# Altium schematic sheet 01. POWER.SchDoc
size A4; DrawnBy: Jaden; DocumentNumber: 1; SheetNumber: 1; SheetTotal: 6
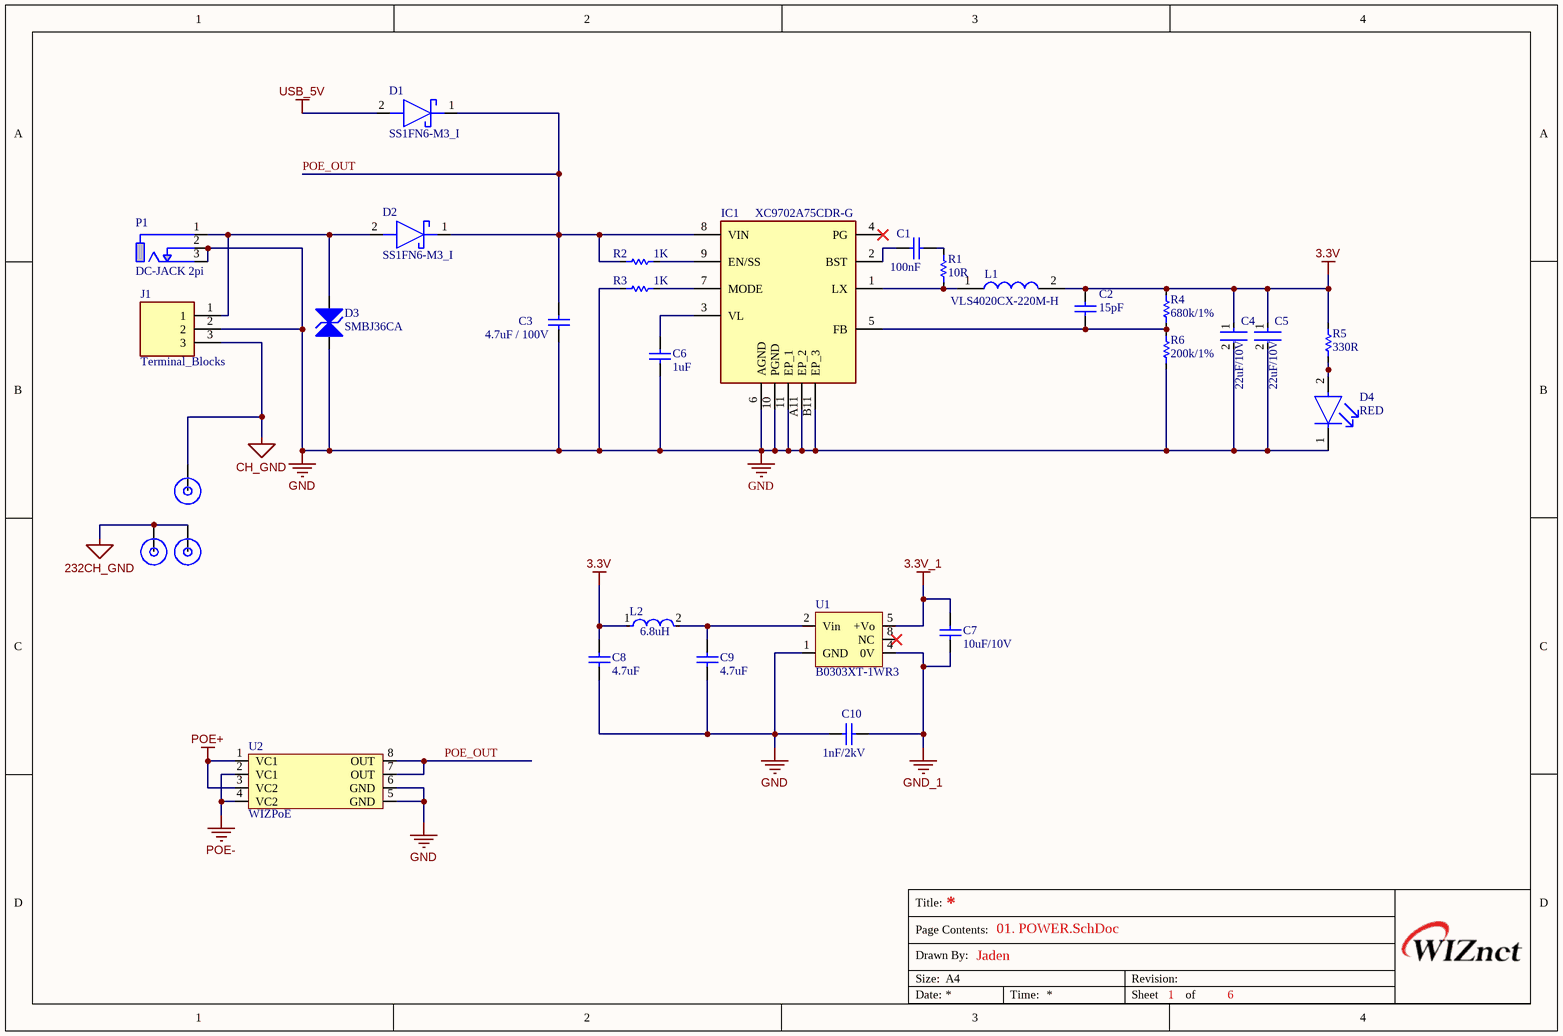
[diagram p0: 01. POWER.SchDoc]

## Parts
C1  100nF  [CAP-0402]
C2  15pF  [CAP-0402]
C3  4.7uF / 100V  [CAP-1210]
C4  22uF/10V  [CAP-1206]
C5  22uF/10V  [CAP-1206]
C6  1uF  [CAP-0603-1]
C7  10uF/10V  [CAP-0603-3]
C8  4.7uF  [CAP-0603-3]
C9  4.7uF  [CAP-0603-3]
C10  1nF/2kV  [CAP-1808]
D1  SS1FN6-M3_I  [SODFL3718X108N]
D2  SS1FN6-M3_I  [SODFL3718X108N]
D3  SMBJ36CA  [DO-214AA/SMB(TVS)]
D4  RED  [KLH-117]
H1  PCB Hole  [M3_HOLE]  (value not drawn)  (no BOM)
H2  PCB Hole  [M3_HOLE]  (value not drawn)  (no BOM)
H3  PCB Hole  [M3_HOLE]  (value not drawn)  (no BOM)
IC1  XC9702A75CDR-G  [XC9135B18CDRG]
J1  Terminal_Blocks  [1803280]
L1  VLS4020CX-220M-H  [XAL40XX]
L2  6.8uH  [FP-SRN2512-MFG]
P1  DC-JACK 2pi  [DC-JACK 2pi]
R1  10R  [RES-0402]
R2  1K  [RES-0402]
R3  1K  [RES-0402]
R4  680k/1%  [RES-0402]
R5  330R  [RES-0402]
R6  200k/1%  [RES-0402]
U1  B0303XT-1WR3  [IB05_XT-W75R3]
U2  WIZPoE  [WIZPoE]

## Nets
3.3V: C2.2 C4.1 C5.1 C8.2 L1.2 L2.1 R4.2 R5.2
3.3V_1: C7.2 U1.5(+Vo)
232CH_GND: H2.1 H3.1
CH_GND: H1.1 J1.3
GND: C3.1 C4.2 C5.2 C6.1 C8.1 C9.1 C10.2 D3.1(A1) D4.1(C) IC1.6(AGND) IC1.10(PGND) IC1.11(EP_1) IC1.A11(EP_2) IC1.B11(EP_3) J1.2 P1.2(GND) P1.3(GND) R3.1 R6.1 U1.1(GND) U2.5(GND) U2.6(GND)
GND_1: C7.1 C10.1 U1.4(0V)
POE+: U2.1(VC1) U2.3(VC2)
POE-: U2.2(VC1) U2.4(VC2)
USB_5V: D1.2(A)
POE_OUT: C3.2 D1.1(K) D2.1(K) IC1.8(VIN) R2.1 U2.7(OUT) U2.8(OUT)
NetC1_1: C1.1 R1.1
NetC1_2: C1.2 IC1.2(BST)
NetC2_1: C2.1 IC1.5(FB) R4.1 R6.2
NetC6_2: C6.2 IC1.3(VL)
NetC9_2: C9.2 L2.2 U1.2(Vin)
NetD2_2: D2.2(A) D3.2(A2) J1.1 P1.1(VCC)
NetD4_2: D4.2(A) R5.1
NetIC1_1: IC1.1(LX) L1.1 R1.2
NetIC1_7: IC1.7(MODE) R3.2
NetIC1_9: IC1.9(EN/SS) R2.2

Not connected (* = marked no-connect by the designer): IC1 4(PG)*; U1 8(NC)*

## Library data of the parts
C1 C2 = CAP-0402: MLCC-0402(1005)
C3 = CAP-1210: MLCC-1210(3225)
C4 C5 = CAP-1206: MLCC-1206(3216); Manufacturer: KEMET; Manufacturer Part Number: C1206X102KGRACTU; Tolerance: 10%; Voltage Rating (DC): 2kV; Capacitance: 1nF; Dielectric: X7R; Dielectric Material: Ceramic
C6-C9 = CAP-0603: MLCC-0603(1608)
C10 = CAP-1808: MLCC-1808(4520)
D1 D2 = SS1FN6-M3_I: Schottky Diode; Manufacturer_Name: Vishay; Manufacturer_Part_Number: SS1FN6-M3/I
D3 = DIODE-TVS (SMB): PartNumber: SMAJ58CA-E3/61; Manufacturer: Vishay Semiconductor; Manufacturer: Vishay Semiconductors; PPPM (W): 400, 300; ID (uA): 2; IFSM: 40 A; VWM (V): 58; VBR Bi-Directional (V): 6.4 to 231; Packing: Tape and Reel
D4 = KLH-117: LED 3MM HIGH EFF GREEN; Manufacturer: Dialight; Manufacturer Part Number: 551-0207F; Viewing Angle: 45°; Lens Size: 5mm; Dominant Wavelength: 563nm; Test Current: 10mA; Power Dissipation: 75mW; Luminous Intensity: 16mcd; Operating Supply Voltage: 2.1V; Reverse Voltage: 3V; Number of LEDs: 1; Lens Style: Diffused; Element Configuration: Single
H1-H3 = PCB Hole: PCB Supporter Hole
IC1 = XC9702A75CDR-G: Integrated Circuit; Manufacturer_Name: Torex
J1 = 1803280: Connector; Manufacturer_Name: Phoenix Contact
L1 = XAL4040-822MEC: Inductor; Manufacturer_Name: COILCRAFT
L2 = IND-1008(2520): SMD IND 1008(2520); Inductance Tolerance: 20%; Core Material: Ferrite; Shielding: Shielded; Max DC Current: 4.7A; Self Resonant Frequency: 330MHz; Test Frequency: 1MHz; Inductance: 240nH; DC Resistance (DCR): 24mR; Saturation Current: 8A
R1-R6 = RES-0402: Chip Resistor 0402(1005)
U1 = IES0103S3V3: Isolate DCDC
